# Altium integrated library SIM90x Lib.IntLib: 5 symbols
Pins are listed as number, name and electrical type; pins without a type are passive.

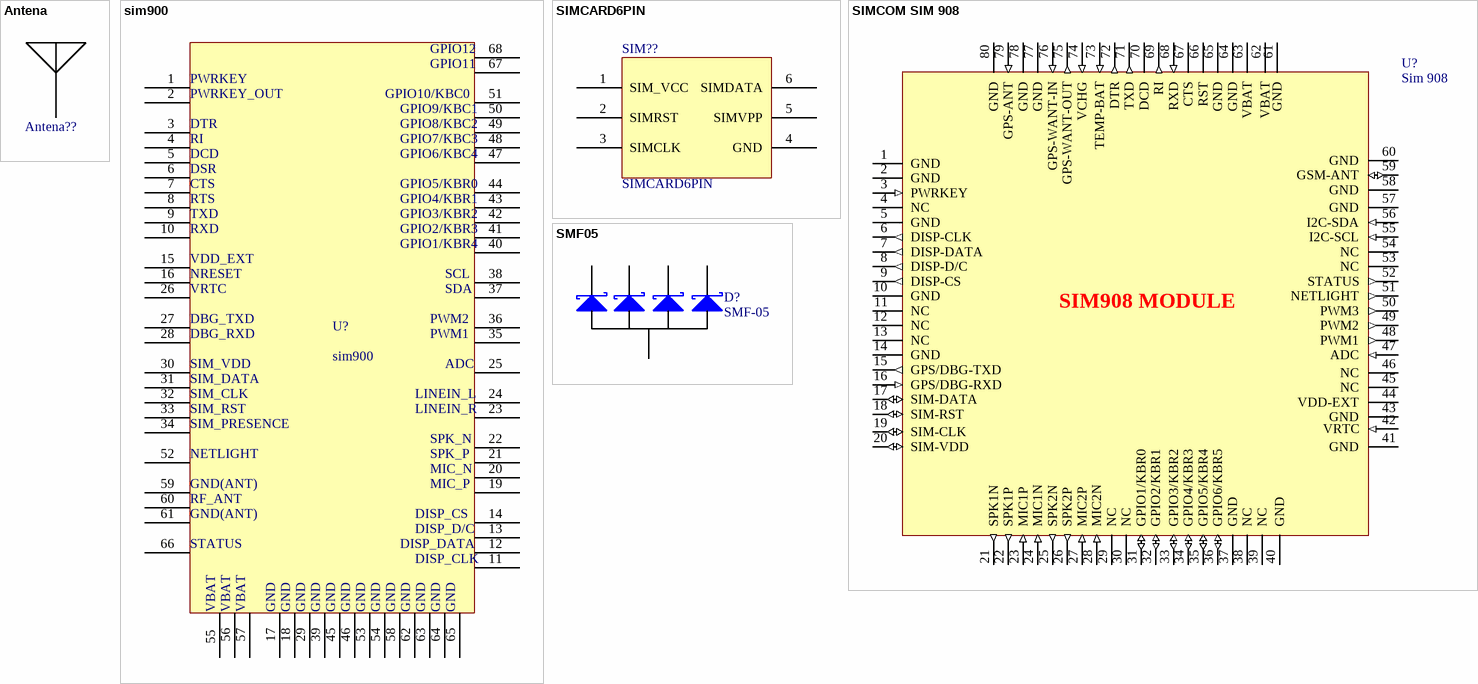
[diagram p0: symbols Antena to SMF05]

## Antena
designator Antena??  (value not drawn)
footprint SMA
footprint U.FL SMD Connector
pins: 1, 2 hidden to GND

## sim900
designator U?
SIMCOM SIM900
footprint Sim900
pins: 1, 2, 3, 4, 5, 6, 7, 8, 9, 10, 11, 12, 13, 14, 15, 16, 17, 18, 19, 20, 21, 22, 23, 24, 25, 26, 27, 28, 29, 30, 31, 32, 33, 34, 35, 36, 37, 38, 39, 40, 41, 42, 43, 44, 45, 46, 47, 48, 49, 50, 51, 52, 53, 54, 55, 56, 57, 58, 59, 60, 61, 62, 63, 64, 65, 66, 67, 68

## SIMCARD6PIN
designator SIM??
footprint SIM HOLDER 2
pins: 1 SIM_VCC, 2 SIMRST, 3 SIMCLK, 4 GND, 5 SIMVPP, 6 SIMDATA

## SIMCOM SIM 908
designator U?, comment Sim 908
SIMCOM SIM908
footprint SIM908 (Simcom SIM908)
pins: 1 GND (power), 2 GND (power), 3 PWRKEY (in), 4 NC, 5 GND (power), 6 DISP-CLK (out), 7 DISP-DATA (out), 8 DISP-D/C (out), 9 DISP-CS (out), 10 GND (power), 11 NC, 12 NC, 13 NC, 14 GND (power), 15 GPS/DBG-TXD (out), 16 GPS/DBG-RXD (in), 17 SIM-DATA (io), 18 SIM-RST (io), 19 SIM-CLK (io), 20 SIM-VDD (io), 21 SPK1N (out), 22 SPK1P (out), 23 MIC1P (in), 24 MIC1N (in), 25 SPK2N (out), 26 SPK2P (out), 27 MIC2P (in), 28 MIC2N (in), 29 NC, 30 NC, 31 GPIO1/KBR0 (io), 32 GPIO2/KBR1 (io), 33 GPIO3/KBR2 (io), 34 GPIO4/KBR3 (io), 35 GPIO5/KBR4 (io), 36 GPIO6/KBR5 (io), 37 GND (power), 38 NC, 39 NC, 40 GND, 41 GND (power), 42 VRTC (in), 43 GND (power), 44 VDD-EXT (power), 45 NC, 46 NC, 47 ADC (in), 48 PWM1 (out), 49 PWM2 (out), 50 PWM3 (out), 51 NETLIGHT (out), 52 STATUS (out), 53 NC, 54 NC, 55 I2C-SCL (in), 56 I2C-SDA (in), 57 GND (power), 58 GND (power), 59 GSM-ANT (io), 60 GND (power), 61 GND (power), 62 VBAT (power), 63 VBAT (power), 64 GND (power), 65 GND (power), 66 RST (power), 67 CTS (power), 68 RXD (in), 69 RI (out), 70 DCD (hiz), 71 TXD (out), 72 DTR (out), 73 TEMP-BAT (in), 74 VCHG (in), 75 GPS-WANT-OUT (out), 76 GPS-WANT-IN (in), 77 GND (power), 78 GND (power), 79 GPS-ANT (in), 80 GND (power)

## SMF05
designator D?, comment SMF-05
TVS Diode Array
footprint SC70-5_N (SOT353, 5-Leads, Body 2x1.3mm, Pitch 0.65mm, Lead Span 2.1mm, IPC Medium Density)
pins: 1 K, 2 K, 3 K, 4 K, 5 K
